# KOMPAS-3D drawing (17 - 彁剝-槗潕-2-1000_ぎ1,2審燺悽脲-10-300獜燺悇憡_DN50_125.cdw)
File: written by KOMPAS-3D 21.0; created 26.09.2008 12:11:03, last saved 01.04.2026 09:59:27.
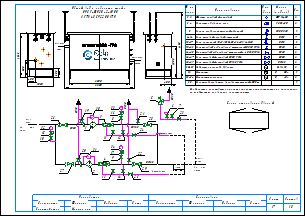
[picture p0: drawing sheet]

Sheets 1-2: A3, landscape

Document properties: Наименование: Макро:21; Автор: RaskoAdmin; Форматы листов документа: 2xA3; Полное имя файла: \\UR38nt01\Departments\КТО\КБ ПУРДГ\Заявки\Прайс-лист на типовые шкафы ГРПШ\ПРДГ_стандарт_20_03_2026\ПРДГ с РДСК\ПРДГ-ШУЭО-2-1000_до1,2МПа_Рвых-10-300кПа_РДСК_DN50_125.cdw

Title block, sheet 1: Наименование: Пункт учета газа / ПУГ-Ш-400-Р / ЛГТИ.485922.001ТУ; designation: ЛГТИ.03.4411141; sheet number: 1; Количество листов документа: 2; organisation: ООО "ЭЛЬСТЕР Газэлектроника"; Форматы листов документа: A3; stored path: C:\Рабочие документы\Компас\ПУГ\Схема.cdw; Разработал: Устинов; Проверил: Кошкин; Утвердил: Кошкин
Title block, sheet 2: sheet number: 2; stored path: D:\Рабочие документы\Заявки\ПУРДГ\ПУРДГ-ШУЭО-2-100-Р 4411220.cdw; designation, second copy: ЛГТИ.03.4411141-

Views: Вид 1, Вид 2
Referenced files: wcvoit.frw
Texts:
  Normal
  Вход
  газа
  PDI
  Выход
  Р=     кПа
  DN125
  DN50
  DN20
  Импульс DN20
  ≥5DN
  HYSWLongFangSong
  № на
  схеме
  Усл.
  обозн.
  Марка
  (модель)
  Кол.
  Фильтр газовый фланцевый
  ФГ 16-50
  Регулятор давления газа
  РДCК-50
  Клапан предохранительный сбросной
  КПС DN20
  Кран шаровой газовый латунный
  DN15
  Кран кнопочный VE-РАСКО-НЗ-1,6-G1/2-М20
  Кран шаровой "под приварку" штуцерный DN20 PN16
  Кран шаровой "под приварку" штуцерный п/п DN20 PN16
  Кран шаровой фланцевый DN50 PN16
  Кран шаровой фланцевый DN125 PN16
  Индикатор перепада давления
  Delta 15
  Манометр
  Манометр-напоромер
  Электрообогреватель взрывозащищенный 400Вт
  0...     МПа
  0...     кПа
  Общий вид и габариты шкафа
  ПРДГ-ШУЭО-2-1000
  Выход газа
  Вход газа
  Схема открывания дверей
  Р=        МПа
  logo-rasko-ge.png
  Предприятие изготовитель может заменять комплектующие на аналогичные,
  не ухудшающие заявленных характеристик.
  Должность
  Конструктор
  Фамилия
  Подпись
  Дата
  Согласовано
  Максимкин
  Лист
  Листов
  POLYLINE_STYLE_0.18_RGB_0_0_0
  POLYLINE_STYLE_0.50_RGB_0_0_0
  POLYLINE_STYLE_0.34_RGB_0_0_0
  PHANTOM_RGB_0_0_0_SC_1_THICK_0.18
  K5LT_THIN_RGB_0_0_0_THICK_0.18
  K5LT32769_RGB_0_0_0_THICK_0.18
  K5LT12_RGB_0_0_0_SC_1_THICK_0.18
  K5LT_DASHED_RGB_0_0_0_SC_1_THICK_0.18
  ACISOTGL_RGB_0_0_0_SC_0.8_THICK_0.25
  CONTINUOUS_RGB_0_127_31_THICK_0.3
  CONTINUOUS_RGB_0_0_255_THICK_0.35
  CONTINUOUS_RGB_255_0_0_THICK_0.35
  POLYLINE_STYLE_0.25_RGB_0_0_0
  CONTINUOUS_RGB_0_0_0_THICK_0.5
  POLYLINE_STYLE_0.35_RGB_0_0_255
  CONTINUOUS_RGB_0_0_0_THICK_0.4
  CONTINUOUS_RGB_0_0_0_THICK_0.35
  Без оформления
Dimensions and other numbers on the sheet: 1; 2; 3; 4; 5; 10; 27; 28; 29; 23; 8; 12; 19; 20; 21; 22; 25; 24; 30; 31; 15; 16; 26; 6; 7; 11; 14; 13; 33; 1, 2; 3, 4; 6-14; 9; 15-17; 18-23; 24-25; 26-27; 28-29; 30-31; 32; 33-34; 35; 400; 1050; 500; 305; 2500; 1565; 2800; 17; 34; 1000; 4130; 18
